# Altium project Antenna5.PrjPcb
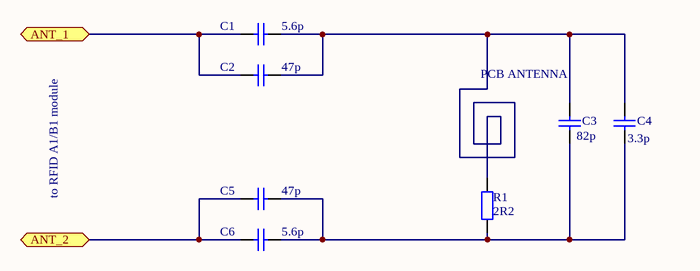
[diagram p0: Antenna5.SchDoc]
1 sheet, 7 parts. Net scope: flat (ports and power ports of the same name join across sheets).

## Sheet Antenna5.SchDoc
size A4

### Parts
C1  5.6p  [0603_CAP]
C2  47p  [0603_CAP]
C3  82p  [0603_CAP]
C4  3.3p  [0603_CAP]
C5  47p  [0603_CAP]
C6  5.6p  [0603_CAP]
R1  2R2  [0603_RES]

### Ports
ANT_1, ANT_2

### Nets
NetC1_1: C1.1 C2.2 C3.2 C4.2 R1.2
NetC1_2: C1.2 C2.1 ; port ANT_1
NetC3_1: C3.1 C4.1 C5.2 C6.1 R1.1
NetC5_1: C5.1 C6.2 ; port ANT_2

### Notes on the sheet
- PCB ANTENNA
- to RFID A1/B1 module

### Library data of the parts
C1-C6 = Cap: Capacitor; Is Mounted: no
R1 = Res2: Resistor; Is Mounted: no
